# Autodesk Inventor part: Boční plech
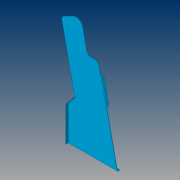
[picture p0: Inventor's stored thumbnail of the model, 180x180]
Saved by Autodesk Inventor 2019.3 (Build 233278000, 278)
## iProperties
Created: 2019-02
Part Number: Boční plech
Material: Ocel, pozinkovaná
Document SubType Name: Plech
Designer: B-hon
Density: 7.85 g/cm^3
Sheet Metal Rule: Výchozí_mm
Appearance: Nebeská modrá – střední
Author: B-hon
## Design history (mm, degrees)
node "Plocha1"
  sketch "Náčrt1"
    geometry: L1 (0, 0)-(-244.44, 1150); L2 (314.881, 0)-(70.441, 1150); L3 (0, 0)-(314.881, 0); L4 (-244.44, 1150)-(70.441, 1150)
    constraints: 8 end point, 2 horizontal, 1 parallel
    dimensions: "d1" = 308 distance between parallel lines of L1 L2; "d2" = 1150 distance from line of L1.end L3; "d3" = 102 deg angle of L3 L1
sketch "Náčrt3"
  geometry: L1 (27.892, 860)-(-97.025, 860); L2 (-97.025, 860)-(-97.025, 480); L3 (-97.025, 480)-(27.892, 480); L4 (27.892, 480)-(27.892, 860); L5 (0, 0)-(-3, 0) reference; 1 further point
  constraints: 8 end point, 2 parallel, 1 horizontal, 1 perpendicular
  dimensions: "d10" = 480 distance between parallel lines of L5 L3; "d23" = 380 distance of L3.end L1.start
extrude "Vysunutí3" cut sketch "Náčrt3" distance "d24" = 1; taper "d25" = 0 deg
node "Obruba2"
sketch "Náčrt6"
  geometry: L1 (-13.139, 1502.331)-(147.613, 746.051); L2 (147.613, 746.051)-(295.063, 777.393); L3 (295.063, 777.393)-(134.311, 1533.672); L4 (134.311, 1533.672)-(-13.139, 1502.331); L5 (70.441, 1150)-(136.077, 841.207) reference; L6 (70.441, 1150)-(136.077, 841.207) reference; 1 further point
  constraints: 8 end point, 4 parallel, 1 perpendicular
  dimensions: "d36" = 8.5 distance between parallel lines of L1 L5
extrude "Vysunutí4" cut sketch "Náčrt6" distance "d37" = 3; taper "d38" = 0 deg
chamfer "Zkosení1" distance "d40" = 19; stored, may be unused: second distance "d41" = 2, angle "d42" = 45 deg
sketch "Náčrt7"
  geometry: L1 (-120.117, 189.338)-(203.274, 189.338); L2 (203.274, 189.338)-(203.274, -49.525); L3 (203.274, -49.525)-(-120.117, -49.525); L4 (-120.117, -49.525)-(-120.117, 189.338); L5 (6, 94.975)-(25, 94.975) reference; 1 further point
  constraints: 8 end point, 2 parallel, 1 horizontal, 1 perpendicular
  dimensions: "d43" = 144.5 distance between parallel lines of L5 L3
extrude "Vysunutí5" cut sketch "Náčrt7" distance "d44" = 10; taper "d45" = 0 deg
sketch "Náčrt12"
  geometry: L1 (-55.86, 1222.341)-(33.587, 801.529); L2 (33.587, 801.529)-(235.178, 844.379); L3 (235.178, 844.379)-(174.093, 1251.655); L4 (174.093, 1251.655)-(-55.86, 1222.341); L5 (157.91, 697.608)-(61.751, 1150) reference; 1 further point
  constraints: 8 end point, 1 parallel, 1 perpendicular
  dimensions: "d80" = 335 distance from line of L5.end L2; "d81" = 100 distance between parallel lines of L5 L1
extrude "Vysunutí8" cut sketch "Náčrt12" distance "d82" = 10; taper "d83" = 0 deg
sketch "Náčrt13"
  geometry: L1 (0, 0)-(-244.44, 1150) reference; L2 (0, 0)-(-155, 0); L3 (-155, 0)-(-155, 330); L4 (-155, 330)-(-87.294, 410.688); L5 (0, 0)-(-244.44, 1150) reference
  constraints: 6 end point, 1 horizontal, 1 perpendicular, 1 point on line
  dimensions: "d85" = 155 distance of L1.start L2.end; "d86" = 330 distance of L2.end L3.end; "d87" = 140 deg angle of L3 L4
extrude "Vysunutí10" join sketch "Náčrt13" distance "d90" = 3; taper "d91" = 0 deg
node "Obruba5"
node "Upravit přímo1"
fillet "Zaoblení9" dims "d114" = 48
sketch "Náčrt17"
  geometry: L1 (-269.669, 979.766)-(44.259, 1139.721); L2 (44.259, 1139.721)-(47.719, 1191.189); L3 (47.719, 1191.189)-(-377.393, 1191.189); L4 (-377.393, 1191.189)-(-269.669, 979.766); L5 (-244.44, 1150)-(-40.483, 1150) reference; L6 (-87.294, 410.688)-(-244.44, 1150) reference; 2 further points
  constraints: 8 end point, 2 point on line, 1 horizontal, 1 perpendicular
  dimensions: "d123" = 27 deg angle of L1 L5; "d124" = 142 distance from line of point (-214.257, 1008) L5
extrude "Vysunutí14" cut sketch "Náčrt17" distance "d125" = 10; taper "d126" = 0 deg
fillet "Zaoblení12" dims "d127" = 64
fillet "Zaoblení13" dims "d128" = 30
sketch "Náčrt18"
  geometry: L1 (-314.881, 0)-(149, 0) reference; L2 (-215.083, 469.511)-(-314.881, 0) reference; 2 further points
  dimensions: "d129" = 60 distance from line of L1 point (-291.904, 60); "d131" = 10 distance from line of point (-291.904, 60) L2
hole "Díra1" sketch "Náčrt18" at (-291.904, 60) diameter "d132" = 6.5; stored, may be unused: countersink angle "d136" = 90 deg, drill point angle "d138" = 118 deg; dims "d133" = 6, "d134" = 4, "d135" = 2, "d137" = 3 (= Tloušťka)
pattern_linear "Obdélníkové pole1" dims "d141" = 180
sketch "Náčrt19"
  geometry: L1 (-141.381, 775.369)-(-157.91, 697.608) reference; L2 (-80.538, 811.509)-(-84.45, 812.341) reference; L3 (87.294, 410.688)-(209.471, 985.483) reference; 2 further points
  dimensions: "d143" = 40 distance from line of point (123.893, 727.162) L2; "d178" = 30 distance from line of L3 point (123.893, 727.162)
hole "Díra2" sketch "Náčrt19" at (123.893, 727.162) diameter "d144" = 6.5; stored, may be unused: countersink angle "d148" = 90 deg, drill point angle "d150" = 118 deg; dims "d145" = 6, "d146" = 4, "d147" = 2, "d149" = 3 (= Tloušťka)
pattern_linear "Obdélníkové pole2" dims "d153" = 150
sketch "Náčrt20"
  geometry: L1 (12.889, 1020.182)-(-23.607, 848.48) reference; L2 (193.746, 1018.451)-(104.546, 1063.9) reference; 2 further points
  dimensions: "d154" = 142 distance from line of point (143.997, 954.013) L1; "d155" = 80 distance from line of point (143.997, 954.013) L2
hole "Díra3" sketch "Náčrt20" at (143.997, 954.013) diameter "d156" = 6.5; stored, may be unused: countersink angle "d160" = 90 deg, drill point angle "d162" = 118 deg; dims "d157" = 6, "d158" = 4, "d159" = 2, "d161" = 3 (= Tloušťka)
pattern_linear "Obdélníkové pole3" dims "d165" = 150
sketch "Náčrt21"
  geometry: L1 (19, 0)-(0, 0) reference; L2 (19, 0)-(19, -215.5) reference; 2 further points
  dimensions: "d166" = 15.3 distance from line of L1 point (10.7, -15.3); "d167" = 8.3 distance from line of L2 point (10.7, -15.3)
hole "Díra4" sketch "Náčrt21" at (10.7, -15.3) diameter "d168" = 6.5; stored, may be unused: countersink angle "d172" = 90 deg, drill point angle "d174" = 118 deg; dims "d169" = 6, "d170" = 4, "d171" = 2, "d173" = 3 (= Tloušťka)
pattern_linear "Obdélníkové pole4" dims "d177" = 90
node "Obruba6"
sketch "Náčrt23"
  geometry: L1 (463.881, 0)-(0, 0) reference; L2 (463.881, -20)-(463.881, 0) reference; 2 further points
  dimensions: "d189" = 10 distance from line of L1 point (428.881, -10); "d190" = 35 distance from line of L2 point (428.881, -10)
hole "Díra5" sketch "Náčrt23" at (428.881, -10) diameter "d191" = 6.4; stored, may be unused: countersink angle "d195" = 90 deg, drill point angle "d197" = 118 deg; dims "d192" = 12, "d193" = 6, "d194" = 2, "d196" = 3 (= Tloušťka)
pattern_linear "Obdélníkové pole5" dims "d200" = 197
node "Těleso1"
feature "Deska1" dims "d4" = 3 (= Tloušťka)
sketch "Náčrt5"
  geometry: L1 (379.5, 0)-(0.5, 0); L2 (0.5, 0)-(0.5, -25); L3 (0.5, -25)-(379.5, -25); L4 (379.5, -25)-(379.5, 0)
  constraints: 8 end point
feature "Deska3" dims "d4" = 3 (= Tloušťka), "d26" = 0.5, "d27" = 1.5 (= HloubkaVýštipu), "d28" = 6 (= MinimálníZbytek), "d29" = 3 (= PřechodovýPoloměr), "d30" = 25, "d31" = 90 deg, "d32" = 3 (= PoloměrOhybu), "d33" = 12 (= VelikostRohovéhoVýštipu), "d34" = 3 (= VelikostMezery), "d35" = 3 (= VelikostJacobihoPoloměru), "MezeraVystřižení" = 0.01
feature "Ohyb2" dims "d4" = 3 (= Tloušťka), "d26" = 0.5, "d27" = 1.5 (= HloubkaVýštipu), "d28" = 6 (= MinimálníZbytek), "d29" = 3 (= PřechodovýPoloměr), "d30" = 25, "d31" = 90 deg, "d32" = 3 (= PoloměrOhybu), "MezeraVystřižení" = 0.01
feature "Roh2" dims "d30" = 25, "d31" = 90 deg, "d33" = 12 (= VelikostRohovéhoVýštipu), "d34" = 3 (= VelikostMezery), "d35" = 3 (= VelikostJacobihoPoloměru)
sketch "Náčrt14"
  geometry: L1 through (-51.166, 0) direction (1, -4.82e-33); L2 through (0, 10) direction (6.16e-33, 1); L3 (0, 20)-(-102.331, 20); L4 (-102.331, 20)-(-102.331, 0)
  constraints: 6 end point, 1 horizontal, 1 perpendicular, 1 vertical
feature "Deska6" dims "d4" = 3 (= Tloušťka), "d92" = 3 (= ŠířkaVýštipu), "d93" = 1.5 (= HloubkaVýštipu), "d94" = 6 (= MinimálníZbytek), "d95" = 3 (= PřechodovýPoloměr), "d96" = 20, "d97" = 90 deg, "d98" = 3 (= PoloměrOhybu), "d99" = 12 (= VelikostRohovéhoVýštipu), "d100" = 3 (= VelikostMezery), "d101" = 3 (= VelikostJacobihoPoloměru), "MezeraVystřižení" = 0.01
feature "Ohyb5" dims "d4" = 3 (= Tloušťka), "d92" = 3 (= ŠířkaVýštipu), "d93" = 1.5 (= HloubkaVýštipu), "d94" = 6 (= MinimálníZbytek), "d95" = 3 (= PřechodovýPoloměr), "d96" = 20, "d97" = 90 deg, "d98" = 3 (= PoloměrOhybu), "MezeraVystřižení" = 0.01
feature "Roh5" dims "d96" = 20, "d97" = 90 deg, "d99" = 12 (= VelikostRohovéhoVýštipu), "d100" = 3 (= VelikostMezery), "d101" = 3 (= VelikostJacobihoPoloměru)
sketch "Náčrt22"
  geometry: L1 through (231.94, 0) direction (-1, -1.2e-18); L2 through (0, -13) direction (0, -1); L3 (0, -26)-(463.881, -26); L4 (463.881, -26)-(463.881, 0)
  constraints: 6 end point, 1 horizontal, 1 perpendicular, 1 vertical
feature "Deska7" dims "d4" = 3 (= Tloušťka), "d179" = 3 (= ŠířkaVýštipu), "d180" = 1.5 (= HloubkaVýštipu), "d181" = 6 (= MinimálníZbytek), "d182" = 3 (= PřechodovýPoloměr), "d183" = 26, "d184" = 90 deg, "d185" = 3 (= PoloměrOhybu), "d186" = 12 (= VelikostRohovéhoVýštipu), "d187" = 3 (= VelikostMezery), "d188" = 3 (= VelikostJacobihoPoloměru), "MezeraVystřižení" = 0.01
feature "Ohyb6" dims "d4" = 3 (= Tloušťka), "d179" = 3 (= ŠířkaVýštipu), "d180" = 1.5 (= HloubkaVýštipu), "d181" = 6 (= MinimálníZbytek), "d182" = 3 (= PřechodovýPoloměr), "d183" = 26, "d184" = 90 deg, "d185" = 3 (= PoloměrOhybu), "MezeraVystřižení" = 0.01
feature "Roh6" dims "d183" = 26, "d184" = 90 deg, "d186" = 12 (= VelikostRohovéhoVýštipu), "d187" = 3 (= VelikostMezery), "d188" = 3 (= VelikostJacobihoPoloměru)
feature "Posunout1" dims "d104" = -1
other parameters: "Tloušťka" = 3 (derived), "KSoučinitel" = 4.4, "PoloměrOhybu" = 3 (= Tloušťka), "ŠířkaVýštipu" = 3 (= Tloušťka), "HloubkaVýštipu" = 1.5 (= 0.5 x Tloušťka), "VelikostRohovéhoVýštipu" = 12 (= 4 x Tloušťka), "MinimálníZbytek" = 6 (= 2 x Tloušťka), "PřechodovýPoloměr" = 3 (= PoloměrOhybu), "VelikostJacobihoPoloměru" = 3 (= PoloměrOhybu), "VelikostMezery" = 3 (= Tloušťka), "d102" = 0, "d103" = 0
